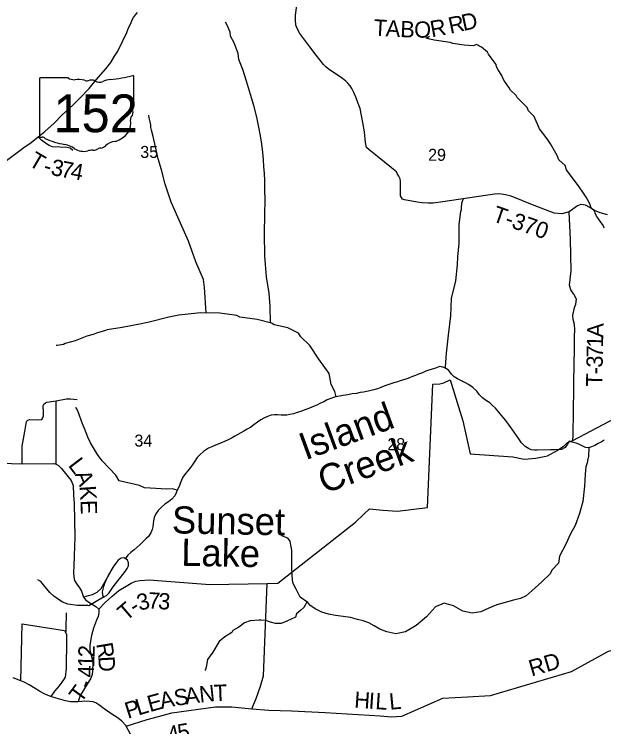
# Model space of a CAD drawing. Extents: x 0 to 34, y 0 to 22.
# Drawn here: x 4.685 to 6.741, y 18.266 to 20.751 of the extents above; entities that cross this region are included whole.
import ezdxf

# ---------------------------------------------------------------- set-up
doc = ezdxf.new("R2010")
doc.units = 0
for name, color, linetype in [('GM_X_County_Road', 7, 'Continuous'), ('GM_X_County_Road_Text', 7, 'Continuous'), ('GM_X_Minor_Lake', 7, 'Continuous'), ('GM_X_Minor_Lake_Text', 7, 'Continuous'), ('GM_X_Minor_River', 7, 'Continuous'), ('GM_X_Minor_River_Text', 7, 'Continuous'), ('GM_X_Section_Text', 7, 'Continuous'), ('GM_X_State_Location', 7, 'Continuous'), ('GM_X_State_Route', 7, 'Continuous'), ('GM_X_State_Shield', 7, 'Continuous'), ('GM_X_Township_Road', 7, 'Continuous'), ('GM_X_Township_Road_Text', 7, 'Continuous')]:
    doc.layers.add(name, color=color, linetype=linetype)

msp = doc.modelspace()

# ---------------------------------------------------------------- linework, layer by layer
at = {"layer": 'GM_X_County_Road'}
for points in [[(4.6388, 19.1858), (4.7126, 19.1836), (4.8239, 19.1841), (4.8317, 19.1822), (4.8394, 19.1768), (4.85, 19.1672), (4.8737, 19.1381), (4.884, 19.1249), (4.8906, 19.1076), (4.8924, 19.0743), (4.8946, 19.0451), (4.8965, 18.9275), (4.8942, 18.8626), (4.8925, 18.8263), (4.8918, 18.8056), (4.8925, 18.7877), (4.8958, 18.7765), (4.9037, 18.7637), (4.9125, 18.7505), (4.9193, 18.7387), (4.9231, 18.729), (4.9271, 18.7179), (4.9352, 18.7076), (4.9507, 18.6973), (4.9608, 18.6914), (4.9703, 18.6855), (4.98, 18.6766), (4.9799, 18.6629), (4.9774, 18.6504), (4.9723, 18.6377), (4.9618, 18.6104), (4.9552, 18.5848), (4.949, 18.5512), (4.9486, 18.5335), (4.9544, 18.5108), (4.9596, 18.4879), (4.9587, 18.4606), (4.9565, 18.4488), (4.9519, 18.4361), (4.9298, 18.3994), (4.9157, 18.3748), (4.9103, 18.3616), (4.9081, 18.3531)], [(6.2654, 18.3708), (6.3464, 18.3757), (6.6287, 18.4593), (6.7574, 18.5293), (6.9222, 18.5733), (7.0449, 18.6084), (7.1902, 18.6821), (7.2829, 18.7485), (7.3608, 18.8138), (7.5525, 19.022), (7.5804, 19.0364), (7.6144, 19.0421), (7.6225, 19.0416)], [(5.076, 18.2684), (5.1493, 18.2917), (5.1886, 18.3014), (5.2344, 18.3146), (5.3866, 18.3351), (5.444, 18.3351), (5.5137, 18.3289), (5.5727, 18.3236), (5.6518, 18.3214), (5.7692, 18.3155), (5.9608, 18.3046), (5.9995, 18.3012), (6.0373, 18.3032), (6.1793, 18.3656), (6.2654, 18.3708)]]:
    msp.add_lwpolyline(points, dxfattribs=at)
at = {"layer": 'GM_X_Minor_Lake'}
for points in [[(4.996, 18.7182), (5.0072, 18.7235), (5.016, 18.7337), (5.0233, 18.7442), (5.0302, 18.7539), (5.0386, 18.7648), (5.0467, 18.775), (5.0554, 18.7867), (5.0642, 18.7976), (5.0726, 18.8081), (5.0788, 18.8179), (5.0838, 18.8279), (5.0839, 18.8374), (5.0798, 18.8472), (5.0682, 18.8548), (5.0583, 18.8537), (5.0479, 18.8473), (5.0402, 18.8376), (5.0325, 18.8271), (5.0256, 18.8162), (5.0199, 18.8053), (5.0177, 18.8015)], [(5.0177, 18.8015), (5.0145, 18.7957), (5.0095, 18.7856), (5.0044, 18.7759), (4.9998, 18.7655), (4.9963, 18.7555), (4.994, 18.7459), (4.992, 18.7364), (4.9927, 18.7261), (4.996, 18.7182)]]:
    msp.add_lwpolyline(points, dxfattribs=at)
at = {"layer": 'GM_X_Minor_River'}
for points in [[(5.5792, 19.6749), (5.578, 19.733), (5.5742, 19.7786), (5.5646, 19.8355), (5.5596, 19.9078), (5.5578, 19.9858), (5.5593, 20.0536), (5.56, 20.1027), (5.5587, 20.1381), (5.5589, 20.1708), (5.5577, 20.1955), (5.5558, 20.2195), (5.5542, 20.2438), (5.5519, 20.2689), (5.5484, 20.2977), (5.5445, 20.3274), (5.5383, 20.3577), (5.5309, 20.3922), (5.5207, 20.4324), (5.5087, 20.4714), (5.4954, 20.5179), (5.4826, 20.5577), (5.4688, 20.5932), (5.4658, 20.6137), (5.4523, 20.6507), (5.4394, 20.6745), (5.4377, 20.6881), (5.4274, 20.7127), (5.4216, 20.7229)], [(6.7426, 20.0046), (6.7402, 20.0126), (6.7247, 20.034), (6.7173, 20.0461), (6.7114, 20.0566), (6.7094, 20.0627), (6.699, 20.0739), (6.6959, 20.0781), (6.6931, 20.0864), (6.6888, 20.097), (6.6798, 20.1132), (6.6682, 20.1301), (6.6554, 20.1493), (6.6395, 20.1715), (6.6241, 20.1907), (6.6105, 20.2083), (6.6061, 20.2235), (6.5842, 20.2437), (6.5791, 20.2581), (6.5557, 20.2992), (6.5433, 20.3168), (6.5166, 20.351), (6.4985, 20.3941), (6.4785, 20.4143), (6.4741, 20.4253), (6.4491, 20.4504), (6.4391, 20.4608), (6.4356, 20.4676), (6.4153, 20.4859), (6.4117, 20.4939), (6.3943, 20.5179), (6.3877, 20.53), (6.3856, 20.5372), (6.3728, 20.5568), (6.3673, 20.5677), (6.3653, 20.5753), (6.3479, 20.5986), (6.339, 20.6114), (6.3358, 20.6193), (6.3144, 20.6364), (6.3052, 20.6412), (6.3021, 20.6435), (6.2968, 20.6457), (6.2852, 20.6405), (6.2541, 20.6434), (6.2151, 20.6485), (6.2056, 20.6522), (6.1495, 20.6604), (6.1344, 20.6635), (6.1214, 20.6679), (6.133, 20.6745)], [(5.3544, 19.7092), (5.349, 19.7984), (5.3451, 19.8262), (5.318, 19.8874), (5.2929, 19.9593), (5.2607, 20.0326), (5.232, 20.0957), (5.2113, 20.1582), (5.1987, 20.2082), (5.1871, 20.2465), (5.1777, 20.2886), (5.1695, 20.325), (5.1639, 20.3462), (5.1618, 20.3557), (5.1617, 20.3644), (5.1588, 20.3754), (5.1559, 20.3894), (5.1543, 20.3985)], [(6.1889, 19.5169), (6.1895, 19.5216), (6.1924, 19.5688), (6.1997, 19.6317), (6.2072, 19.6996), (6.2104, 19.7591), (6.2248, 19.8217), (6.2307, 19.877), (6.2317, 19.9048), (6.2366, 19.9521), (6.2372, 19.9795), (6.2365, 19.9982), (6.2373, 20.0172), (6.2422, 20.063), (6.2444, 20.0702), (6.2447, 20.0744), (6.2466, 20.0916), (6.2491, 20.1027), (6.2528, 20.1096)], [(5.8084, 19.4168), (5.8031, 19.4348), (5.7909, 19.4601), (5.7831, 19.498), (5.7471, 19.5485), (5.7164, 19.5963), (5.6842, 19.6258), (5.6768, 19.6387), (5.639, 19.6571), (5.5916, 19.6677), (5.5828, 19.674), (5.5327, 19.6869), (5.4717, 19.695), (5.461, 19.7002), (5.4027, 19.7083), (5.3365, 19.7095), (5.3244, 19.7089), (5.2595, 19.7018), (5.2245, 19.6947), (5.156, 19.6776), (5.1217, 19.6702), (5.0614, 19.6581), (5.0097, 19.6508), (5.0034, 19.6476), (4.9725, 19.6384), (4.9605, 19.6344), (4.9383, 19.6279), (4.9263, 19.6239), (4.8981, 19.6116), (4.8628, 19.6023), (4.8571, 19.5987), (4.8353, 19.5957), (4.8319, 19.5953)], [(6.6543, 19.2519), (6.6447, 19.2554), (6.6305, 19.2588), (6.6198, 19.2619), (6.6148, 19.2518), (6.6064, 19.2402), (6.5937, 19.2325), (6.5705, 19.2318), (6.5557, 19.2321), (6.5089, 19.2306), (6.4994, 19.2307), (6.4884, 19.2319), (6.4783, 19.2365), (6.4667, 19.2438), (6.4546, 19.2559), (6.445, 19.2705), (6.437, 19.2813), (6.4291, 19.2932), (6.4203, 19.3055), (6.4112, 19.3178), (6.4025, 19.3293), (6.3934, 19.3408), (6.3855, 19.3508), (6.3748, 19.3638), (6.3638, 19.3768), (6.3536, 19.3868), (6.3438, 19.3956), (6.3318, 19.4028), (6.3182, 19.4138), (6.3068, 19.4249), (6.2981, 19.436), (6.284, 19.4493), (6.2696, 19.4595), (6.2588, 19.466), (6.2468, 19.4717), (6.2306, 19.4796), (6.2194, 19.4861), (6.2103, 19.4961), (6.2004, 19.5084), (6.1892, 19.5168), (6.1795, 19.5203), (6.1681, 19.5222), (6.1572, 19.5184), (6.1421, 19.513), (6.1308, 19.5092), (6.1207, 19.5059), (6.1087, 19.5005), (6.0951, 19.4955), (6.0846, 19.491), (6.0741, 19.4873), (6.064, 19.4835), (6.0542, 19.4798), (6.0425, 19.4764), (6.0316, 19.4726), (6.0184, 19.468), (6.0086, 19.4654), (5.9988, 19.462), (5.9883, 19.4583), (5.9778, 19.4549), (5.9642, 19.4491), (5.9518, 19.4446), (5.9394, 19.4407), (5.9247, 19.4372), (5.9141, 19.435), (5.9035, 19.4335), (5.8914, 19.4316), (5.8789, 19.4289), (5.8638, 19.4266), (5.8483, 19.4238), (5.8324, 19.421), (5.8131, 19.4177), (5.8018, 19.4155), (5.7898, 19.4113), (5.7766, 19.4059), (5.765, 19.3998), (5.7538, 19.3945), (5.7399, 19.388), (5.7256, 19.3822), (5.7125, 19.3765), (5.699, 19.3711), (5.6851, 19.3661), (5.6715, 19.3615), (5.6591, 19.3577), (5.6466, 19.3546), (5.6364, 19.3531), (5.6266, 19.3525), (5.6163, 19.3533), (5.6033, 19.354), (5.5927, 19.3541), (5.5813, 19.3529), (5.5681, 19.3487), (5.5554, 19.3422), (5.5453, 19.3362), (5.5338, 19.3282), (5.5211, 19.319), (5.5103, 19.3115), (5.498, 19.3042), (5.4864, 19.297), (5.4752, 19.2906), (5.4651, 19.2853), (5.455, 19.2793)], [(5.2533, 19.0918), (5.2377, 19.0954), (5.2158, 19.0946), (5.1791, 19.0967), (5.1397, 19.0998), (5.1218, 19.1075), (5.0508, 19.1242), (5.0392, 19.1431), (4.9918, 19.1933), (4.9759, 19.2158), (4.9507, 19.2565), (4.9416, 19.2758), (4.9302, 19.3068), (4.9231, 19.3223), (4.908, 19.3643), (4.9025, 19.3772), (4.8991, 19.3786)], [(5.455, 19.2793), (5.445, 19.2736), (5.4318, 19.2671), (5.4187, 19.2614), (5.4026, 19.2544), (5.3872, 19.2482), (5.3741, 19.2421), (5.3632, 19.2372), (5.3457, 19.2256), (5.3319, 19.2145), (5.3231, 19.2047), (5.3155, 19.1922), (5.3082, 19.1817), (5.2998, 19.1708), (5.2903, 19.1591), (5.2819, 19.1489), (5.2731, 19.1365), (5.2681, 19.1264), (5.2639, 19.1149), (5.26, 19.1045), (5.2532, 19.0917), (5.2497, 19.0821), (5.2451, 19.0709), (5.2352, 19.0595), (5.2226, 19.0504), (5.2099, 19.042), (5.1984, 19.0321), (5.187, 19.0207), (5.1786, 19.0083), (5.1737, 18.9963), (5.1714, 18.9844), (5.1694, 18.9741), (5.1682, 18.9638), (5.1662, 18.9542), (5.162, 18.9419), (5.1536, 18.9302), (5.144, 18.9211), (5.1337, 18.9113), (5.1241, 18.9019), (5.1138, 18.892), (5.1034, 18.8829), (5.0919, 18.8735), (5.0816, 18.864), (5.0721, 18.8522)], [(6.7428, 19.2654), (6.7316, 19.2589), (6.7215, 19.2537), (6.7096, 19.2472), (6.6987, 19.2427), (6.6878, 19.2385), (6.6778, 19.2401), (6.6655, 19.2454), (6.6543, 19.2519)], [(6.6894, 19.2392), (6.6878, 19.2091), (6.6857, 19.1999), (6.6846, 19.1957), (6.6843, 19.1896), (6.6789, 19.1724), (6.6756, 19.1468), (6.6741, 19.1057), (6.6678, 19.0516), (6.6561, 19.0095), (6.6409, 18.9682), (6.6255, 18.9386), (6.6091, 18.903), (6.5872, 18.8608), (6.5834, 18.8371), (6.5601, 18.812), (6.5546, 18.7994), (6.5249, 18.7711), (6.5022, 18.751), (6.4705, 18.7223), (6.4506, 18.7136), (6.4265, 18.7075), (6.3686, 18.6917), (6.3405, 18.6798), (6.312, 18.6671), (6.2818, 18.6625), (6.2495, 18.6695), (6.2167, 18.688), (6.1848, 18.6977), (6.1548, 18.6839), (6.1225, 18.6499), (6.0867, 18.6189), (6.0501, 18.597), (6.0154, 18.5903), (5.9847, 18.5966), (5.9603, 18.6061), (5.9401, 18.6176), (5.9214, 18.6287), (5.9023, 18.6356), (5.8818, 18.6402), (5.8579, 18.6474), (5.8318, 18.6511), (5.806, 18.6541), (5.7813, 18.659), (5.7578, 18.6662), (5.7349, 18.6769), (5.7161, 18.6902), (5.7096, 18.6996), (5.6824, 18.7182), (5.6683, 18.7465), (5.6573, 18.768), (5.6539, 18.7938), (5.6533, 18.8238), (5.6533, 18.8455), (5.6538, 18.8824), (5.6501, 18.8999), (5.6476, 18.9128), (5.6391, 18.9236), (5.6296, 18.9273), (5.6189, 18.9321)], [(4.996, 18.7182), (4.9454, 18.6876), (4.9423, 18.6895), (4.9121, 18.6886), (4.9061, 18.6885), (4.8716, 18.6932), (4.8537, 18.7002), (4.8231, 18.7213), (4.8096, 18.7344), (4.7876, 18.7615), (4.7783, 18.7727), (4.7673, 18.779)], [(5.7057, 18.7023), (5.6995, 18.69), (5.6951, 18.6815), (5.6843, 18.6722), (5.6698, 18.6594), (5.6655, 18.6483), (5.6362, 18.6338), (5.6159, 18.6266), (5.5967, 18.6266), (5.5792, 18.6309), (5.5613, 18.6367), (5.5451, 18.6379), (5.5394, 18.6378), (5.5084, 18.635), (5.4881, 18.629), (5.4684, 18.6135), (5.4478, 18.6017), (5.4437, 18.5948), (5.4194, 18.5799), (5.3993, 18.5629), (5.378, 18.5268), (5.3596, 18.5006), (5.3544, 18.4739), (5.3526, 18.4659), (5.3501, 18.462)]]:
    msp.add_lwpolyline(points, dxfattribs=at)
at = {"layer": 'GM_X_State_Route'}
for points in [[(4.7686, 20.3232), (4.7915, 20.3419), (4.8243, 20.3713), (4.8529, 20.3996), (4.8891, 20.4335), (4.916, 20.4601), (4.9471, 20.4918), (4.9709, 20.5227), (5.0046, 20.5611), (5.0219, 20.5832), (5.0354, 20.6045), (5.0463, 20.6227), (5.078, 20.6872), (5.0842, 20.7037), (5.0915, 20.7183), (5.0969, 20.7312), (5.1014, 20.7401), (5.1085, 20.7491), (5.1156, 20.7566)], [(4.6536, 20.2377), (4.7192, 20.2863), (4.7443, 20.3039), (4.7686, 20.3232)], [(5.0753, 18.2691), (5.0601, 18.2856), (5.048, 18.2964), (5.0223, 18.3128), (4.9991, 18.3286), (4.9803, 18.3427), (4.9692, 18.3491), (4.9604, 18.3527), (4.9482, 18.3547), (4.9318, 18.3551), (4.9212, 18.354), (4.9081, 18.3531), (4.8818, 18.3532), (4.8635, 18.3568), (4.8472, 18.3617), (4.8318, 18.3662), (4.8131, 18.3717), (4.7917, 18.3796), (4.7733, 18.3901), (4.7588, 18.3995), (4.7377, 18.4123), (4.72, 18.4221), (4.7079, 18.4261), (4.6818, 18.4369)], [(5.2067, 17.9332), (5.2, 17.9409), (5.1919, 17.9502), (5.1833, 17.9636), (5.1744, 17.9785), (5.1653, 17.9986), (5.161, 18.0093), (5.1553, 18.0229), (5.1492, 18.0374), (5.1425, 18.055), (5.1391, 18.0676), (5.136, 18.0806), (5.1344, 18.1123), (5.1338, 18.1322), (5.1318, 18.1529), (5.1253, 18.1757), (5.076, 18.2684), (5.0753, 18.2691)]]:
    msp.add_lwpolyline(points, dxfattribs=at)
at = {"layer": 'GM_X_State_Shield'}
for p, q in [((4.773, 20.5255), (4.773, 20.3254)), ((4.8728, 20.529), (4.7762, 20.529)), ((5.1026, 20.4292), (5.1026, 20.5339)), ((5.1026, 20.4293), (5.1026, 20.4292))]:
    msp.add_line(p, q, dxfattribs=at)
for centre, major_axis, start_param, end_param in [((4.7768, 20.5259), (0.00382, 0), 1.712693, 3.28349), ((4.8958, 20.5522), (0.037, 0), 4.042523, 4.731795), ((4.9852, 20.8018), (0.3495, 0), 4.814394, 5.042369), ((5.0989, 20.5344), (0.00367, 0), 6.141152, 7.989035), ((4.908, 20.4166), (0.133, 0), 1.404758, 1.657858), ((4.9382, 20.527), (0.0107, 0), 3.836095, 5.185415), ((4.9539, 20.5038), (0.0222, 0), 0.950623, 2.079405), ((4.9826, 20.5356), (0.0267, 0), 4.081561, 5.145723), ((5.0298, 20.4678), (0.0703, 0), 1.699011, 2.107814), ((5.1017, 20.4215), (0.00568, 0), 1.883978, 3.671073), ((5.0987, 20.4288), (0.00393, 0), 5.05454, 6.418171), ((5.0656, 20.4083), (0.0341, 0), 5.934695, 6.695948), ((5.0048, 20.3721), (0.0874, 0), 5.101752, 6.440018), ((5.1157, 20.3854), (0.0248, 0), 2.387724, 3.262537), ((4.7768, 20.325), (0.00385, 0), 3.00124, 4.508301), ((4.7774, 20.3454), (0.0294, 0), 4.665946, 4.897461), ((4.7834, 20.3138), (0.0106, 0), 0.519207, 1.627899), ((4.9172, 20.4936), (0.2524, 0), 4.195997, 4.488961), ((5.0416, 20.2692), (0.0479, 0), 1.647645, 2.488434), ((4.842, 20.2355), (0.079, 0), 0.823519, 1.323587), ((4.9274, 20.3129), (0.0501, 0), 4.026481, 4.996735), ((4.9564, 20.2437), (0.0412, 0), 1.495662, 1.94098), ((4.96, 20.2979), (0.0267, 0), 4.691044, 5.507374), ((4.9842, 20.2785), (0.00752, 0), 1.147584, 2.315152), ((4.981, 20.306), (0.0282, 0), 4.937069, 5.64225)]:
    msp.add_ellipse(centre, major_axis=major_axis, ratio=0.8, start_param=start_param, end_param=end_param, dxfattribs=at)
at = {"layer": 'GM_X_Township_Road'}
msp.add_line((6.633, 19.2641), (6.634, 19.2823), dxfattribs=at)
for points in [[(6.62, 20.0615), (6.5944, 20.0546), (6.5686, 20.0575), (6.4928, 20.086), (6.4181, 20.1161), (6.3981, 20.1214), (6.3848, 20.1237), (6.3756, 20.1241), (6.3599, 20.1236), (6.3049, 20.1156), (6.2348, 20.1047), (6.1804, 20.0964), (6.1459, 20.0921), (6.1284, 20.0922), (6.1082, 20.0931), (6.0904, 20.096), (6.0462, 20.1035), (6.0396, 20.1066), (6.0357, 20.1118), (6.0327, 20.1179), (6.0319, 20.1234), (6.0326, 20.1681), (6.0309, 20.177), (6.0267, 20.1864), (6.021, 20.1957), (6.0177, 20.2009), (6.0004, 20.2155), (5.9525, 20.2547), (5.923, 20.2776), (5.914, 20.2866), (5.9102, 20.3039), (5.9064, 20.341), (5.9012, 20.374), (5.8915, 20.4222), (5.8846, 20.4394), (5.8775, 20.459), (5.8698, 20.4778), (5.8628, 20.4925), (5.8568, 20.5013), (5.8489, 20.5108), (5.8415, 20.5176), (5.8296, 20.5274), (5.7802, 20.5608), (5.7719, 20.5678), (5.764, 20.5758), (5.7376, 20.6086), (5.7085, 20.647), (5.681, 20.6842), (5.6739, 20.697), (5.6671, 20.7127), (5.6661, 20.7307), (5.6666, 20.7478), (5.671, 20.7813)], [(4.89, 20.2756), (4.8805, 20.2838), (4.8688, 20.2863), (4.8192, 20.2887), (4.8066, 20.2936), (4.7946, 20.3008), (4.7802, 20.3116), (4.7686, 20.3232)], [(6.7538, 20.0515), (6.729, 20.0588), (6.7089, 20.0664), (6.692, 20.0766), (6.6773, 20.0849), (6.6606, 20.087), (6.649, 20.0833), (6.62, 20.0615)], [(6.6364, 19.4473), (6.6367, 19.4675), (6.6394, 19.5866), (6.6391, 19.6288), (6.6405, 19.6498), (6.6389, 19.6691), (6.634, 19.6864), (6.6326, 19.7004), (6.6393, 19.7288), (6.6437, 19.7404), (6.646, 19.7569), (6.6366, 19.7742), (6.6353, 19.7765), (6.6264, 19.7898), (6.6211, 19.8063), (6.6272, 19.8563), (6.6246, 19.9654), (6.62, 20.0615)], [(4.98, 18.6766), (5.0028, 18.6994), (5.0253, 18.7201), (5.0504, 18.7417), (5.0756, 18.7565), (5.0935, 18.7666), (5.109, 18.7734), (5.124, 18.776), (5.1558, 18.7781), (5.3677, 18.7623), (5.567, 18.7658), (5.6048, 18.7664), (5.8751, 18.9794), (5.9044, 19.0081), (5.9236, 19.0264), (5.971, 19.022), (6.0218, 19.0185), (6.1267, 19.0306), (6.1455, 19.4608), (6.1693, 19.462), (6.1828, 19.4657), (6.2049, 19.4757), (6.2498, 19.3329), (6.2757, 19.2176), (6.4238, 19.2073), (6.4633, 19.1998), (6.5045, 19.2029), (6.5444, 19.2113), (6.5785, 19.2295), (6.6011, 19.2452), (6.6027, 19.2463), (6.605, 19.2486)], [(6.605, 19.2486), (6.6142, 19.2576), (6.633, 19.2641), (6.9532, 19.4333)], [(6.634, 19.2823), (6.6342, 19.2841), (6.6364, 19.4473)], [(4.8317, 19.1822), (4.8312, 19.4025), (4.8672, 19.4096), (4.8812, 19.4103), (4.9046, 19.4073)], [(4.7126, 19.1836), (4.7125, 19.245), (4.7217, 19.2962), (4.7281, 19.3309), (4.7325, 19.3356), (4.7383, 19.3371), (4.7668, 19.3362), (4.781, 19.3375), (4.7846, 19.343), (4.7866, 19.3466), (4.7873, 19.3506), (4.7875, 19.3665), (4.7865, 19.3816), (4.7867, 19.3868), (4.7882, 19.3915), (4.7939, 19.3963), (4.7994, 19.3985), (4.8312, 19.4025)], [(4.9271, 18.7179), (4.9392, 18.7223), (4.9581, 18.7273), (4.9749, 18.7359), (4.988, 18.7479), (5.0159, 18.7972), (5.03, 18.8231)], [(5.5137, 18.3289), (5.5293, 18.3642), (5.5443, 18.4078), (5.5541, 18.4437), (5.567, 18.7658)], [(4.8647, 18.5947), (4.8664, 18.5996), (4.8668, 18.6093), (4.8671, 18.6634)], [(4.7079, 18.4261), (4.7127, 18.6256), (4.8606, 18.6017), (4.8678, 18.5896), (4.8678, 18.546), (4.866, 18.494), (4.866, 18.4693), (4.8632, 18.4394), (4.857, 18.4292), (4.8415, 18.4093), (4.8257, 18.3907), (4.8131, 18.3717)]]:
    msp.add_lwpolyline(points, dxfattribs=at)

# ---------------------------------------------------------------- texts
at = {"layer": 'GM_X_County_Road_Text'}
for s, height, rotation, p in [('D', 0.0568, 12.2862, (6.2517, 20.6925)), ('T', 0.0568, 356.5694, (5.9371, 20.677)), ('A', 0.0568, 356.6673, (5.9797, 20.6745)), ('B', 0.0568, 357.2569, (6.0302, 20.6716)), ('O', 0.0568, 359.9624, (6.0798, 20.6693)), ('R', 0.0568, 10.4986, (6.1411, 20.6703)), ('R', 0.0568, 12.0892, (6.2058, 20.6827)), ('L', 0.0568, 307.3773, (4.8712, 19.1773)), ('A', 0.0568, 292.2195, (4.895, 19.147)), ('K', 0.0568, 274.0067, (4.9128, 19.1053)), ('E', 0.0568, 271.7188, (4.9163, 19.0561)), ('R', 0.0568, 279.4963, (4.9709, 18.5553)), ('RD', 0.05682, 16.4177, (6.4892, 18.4412)), ('D', 0.0568, 273.2073, (4.9784, 18.5109)), ('T', 0.0568, 2.1519, (5.3818, 18.3555)), ('A', 0.0568, 12.1108, (5.1983, 18.328)), ('S', 0.0568, 8.2148, (5.2462, 18.3383)), ('A', 0.0568, 7.5036, (5.2839, 18.3438)), ('N', 0.0568, 6.0948, (5.3331, 18.3503)), ('H', 0.0568, 356.019, (5.8696, 18.3329)), ('L', 0.0568, 16.5712, (5.1177, 18.305)), ('E', 0.0568, 15.3014, (5.1581, 18.317)), ('I', 0.0568, 356.0226, (5.9195, 18.3294)), ('L', 0.0568, 356.2885, (5.9431, 18.3278)), ('L', 0.0568, 5.4297, (5.9952, 18.3252)), ('P', 0.0568, 17.4101, (5.0813, 18.2936)), ('4', 0.0568, 13.852, (5.2266, 18.2092)), ('5', 0.0568, 9.4409, (5.2595, 18.2173))]:
    msp.add_text(s, height=height, rotation=rotation, dxfattribs=at).set_placement(p)
at = {"layer": 'GM_X_Minor_Lake_Text'}
for s, rotation, p in [('Sunset', 358.9676, (5.2346, 18.9407)), ('Lake', 358.9681, (5.2671, 18.8276))]:
    msp.add_text(s, height=0.09471, rotation=rotation, dxfattribs=at).set_placement(p)
at = {"layer": 'GM_X_Minor_River_Text'}
for s, rotation, p in [('Island', 20.13, (5.7005, 19.195)), ('Creek', 20.1286, (5.766, 19.0777))]:
    msp.add_text(s, height=0.09474, rotation=rotation, dxfattribs=at).set_placement(p)
at = {"layer": 'GM_X_Section_Text'}
for s, p in [('35', (5.1247, 20.2498)), ('29', (6.1285, 20.2398)), ('34', (5.1043, 19.2432)), ('28', (5.9864, 19.2307))]:
    msp.add_text(s, height=0.04186, rotation=0, dxfattribs=at).set_placement(p)
at = {"layer": 'GM_X_State_Location'}
for s in ['s', 'r']:
    msp.add_text(s, height=0.000189, dxfattribs=at).set_placement((4.9341, 20.4122))
msp.add_text('152', height=0.000189, rotation=0, dxfattribs=at).set_placement((4.8672, 20.3984))
at = {"layer": 'GM_X_State_Shield'}
msp.add_text('152', height=0.13184, dxfattribs=at).set_placement((4.822, 20.3395))
at = {"layer": 'GM_X_Township_Road_Text'}
for s, height, rotation, p in [('T', 0.0568, 329.7206, (4.7318, 20.2257)), ('3', 0.0568, 349.1525, (4.8103, 20.1911)), ('7', 0.0568, 349.5521, (4.8449, 20.1844)), ('4', 0.0568, 349.5502, (4.879, 20.1782)), ('-', 0.0568, 345.1375, (4.7838, 20.198)), ('T-370', 0.05682, 340.7819, (6.3487, 20.0306)), ('A', 0.0568, 88.007, (6.739, 19.6228)), ('1', 0.0568, 88.7978, (6.7383, 19.588)), ('7', 0.0568, 88.9591, (6.7377, 19.553)), ('3', 0.0568, 89.0164, (6.7371, 19.5181)), ('-', 0.0568, 89.0326, (6.7367, 19.4947)), ('T', 0.0568, 89.0228, (6.7359, 19.4522)), ('3', 0.0568, 15.6709, (5.122, 18.6698)), ('7', 0.0568, 357.1418, (5.1509, 18.6787)), ('3', 0.0568, 355.9845, (5.1856, 18.677)), ('T', 0.0568, 40.6473, (5.0759, 18.6326)), ('-', 0.0568, 32.7807, (5.1065, 18.659)), ('2', 0.0568, 88.5622, (4.9651, 18.5077)), ('1', 0.0568, 88.194, (4.964, 18.4723)), ('4', 0.0568, 88.6761, (4.9632, 18.4374)), ('T', 0.0568, 53.9213, (4.9179, 18.3463)), ('-', 0.0568, 68.8952, (4.9506, 18.3948))]:
    msp.add_text(s, height=height, rotation=rotation, dxfattribs=at).set_placement(p)

doc.saveas('drawing.dxf')
